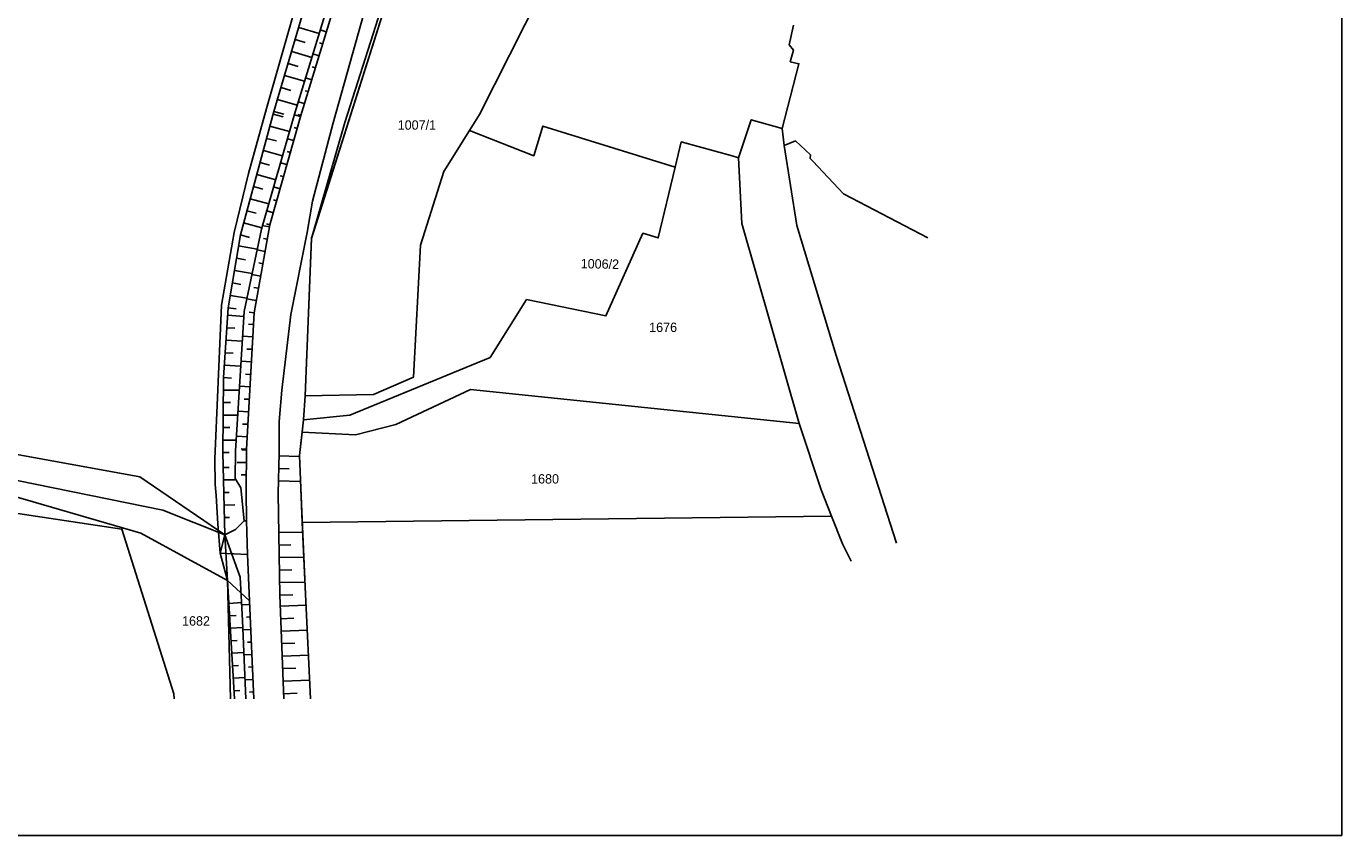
# Model space of a CAD drawing. Extents: x -583470 to -583050, y -1165714 to -1165417.
# Drawn here: x -583260.4 to -583050.1, y -1165714.3 to -1165584.9 of the extents above; entities that cross this region are included whole.
import ezdxf

# ---------------------------------------------------------------- set-up
doc = ezdxf.new("R2010")
doc.units = 0
for name, color, linetype in [('21', 7, 'Continuous'), ('37', 7, 'Continuous'), ('38', 7, 'Continuous'), ('42', 7, 'Continuous'), ('60', 7, 'Continuous'), ('62', 7, 'Continuous'), ('Kabel_soucasny', 7, 'Continuous'), ('Rám', 7, 'Continuous'), ('Šrafy', 7, 'Continuous')]:
    doc.layers.add(name, color=color, linetype=linetype)

msp = doc.modelspace()

# ---------------------------------------------------------------- linework, layer by layer
msp.add_lwpolyline([(-583050.1, -1165714.31), (-583470.1, -1165714.31), (-583470.1, -1165417.31), (-583050.1, -1165417.31)], close=True)
at = {"layer": '21'}
for points in [[(-583228.99, -1165653.07), (-583228.87, -1165641.09), (-583228.11, -1165629.9), (-583226.18, -1165618.27), (-583220.81, -1165598.53), (-583210.74, -1165564.34), (-583206.27, -1165549.49), (-583193.05, -1165509.63), (-583187.62, -1165491.96), (-583180.14, -1165470.95), (-583173.68, -1165449.56)], [(-583197.17, -1165563.17), (-583214.79, -1165618.82), (-583215.85, -1165644.01)], [(-583215.85, -1165644.01), (-583216.1, -1165647.85)], [(-583216.74, -1165653.51), (-583216.1, -1165647.85)], [(-583228.99, -1165653.07), (-583228.69, -1165666.2)], [(-583216.43, -1165661.3), (-583216.74, -1165653.51)], [(-583214.97, -1165692.44), (-583215.79, -1165675.68), (-583216.43, -1165661.3)], [(-583228.25, -1165673.5), (-583228.69, -1165666.2)], [(-583227.11, -1165692.44), (-583228.25, -1165673.5)]]:
    msp.add_lwpolyline(points, dxfattribs=at)
at = {"layer": '37'}
msp.add_lwpolyline([(-583225.23, -1165664), (-583225.6, -1165663.97)], dxfattribs=at)
at = {"layer": '38'}
for points in [[(-583175.32, -1165449.44), (-583181.94, -1165470.41), (-583188.9, -1165491.39), (-583194.56, -1165508.91), (-583207.56, -1165548.63), (-583212.15, -1165563.51), (-583221.98, -1165598.06), (-583224.87, -1165608.46), (-583227.16, -1165617.88), (-583229.21, -1165629.48), (-583230.26, -1165654.06)], [(-583230.26, -1165654.06), (-583230.19, -1165658.17), (-583230.05, -1165659.91), (-583229.77, -1165664.47), (-583229.4, -1165669.14), (-583228.25, -1165673.5)], [(-583228.69, -1165666.2), (-583226.94, -1165665.36), (-583225.6, -1165663.97)], [(-583229.4, -1165669.14), (-583228.69, -1165666.2)], [(-583229.4, -1165669.14), (-583225.03, -1165669.36)], [(-583227.77, -1165692.44), (-583228.25, -1165673.5)]]:
    msp.add_lwpolyline(points, dxfattribs=at)
at = {"layer": '42'}
for points in [[(-583171.13, -1165449.75), (-583178.31, -1165472.16), (-583184.97, -1165493.01), (-583190.34, -1165511.2), (-583202.91, -1165551.09), (-583207.05, -1165564.64), (-583217.53, -1165598.97), (-583222.81, -1165617.33), (-583225.6, -1165630.49), (-583226.96, -1165652.83), (-583227.01, -1165657.21), (-583226.1, -1165658.69), (-583225.6, -1165663.97)], [(-583209.49, -1165600.28), (-583201.68, -1165575.91), (-583199.68, -1165567.9)], [(-583214.79, -1165618.82), (-583209.49, -1165600.28)], [(-583225.84, -1165679.92), (-583225.33, -1165692.44)]]:
    msp.add_lwpolyline(points, dxfattribs=at)
at = {"layer": '60'}
for points in [[(-583216.85, -1165585.1), (-583213.59, -1165586.06)], [(-583212.44, -1165585.8), (-583213.42, -1165585.5)], [(-583217.42, -1165587.02), (-583215.8, -1165587.5)], [(-583213.02, -1165587.71), (-583213.51, -1165587.56)], [(-583217.98, -1165588.94), (-583214.76, -1165589.89)], [(-583213.6, -1165589.62), (-583214.59, -1165589.33)], [(-583218.55, -1165590.86), (-583216.95, -1165591.33)], [(-583214.19, -1165591.54), (-583214.68, -1165591.39)], [(-583219.11, -1165592.77), (-583215.93, -1165593.71)], [(-583214.77, -1165593.45), (-583215.75, -1165593.15)], [(-583219.68, -1165594.69), (-583218.09, -1165595.16)], [(-583215.35, -1165595.36), (-583215.85, -1165595.21)], [(-583220.24, -1165596.61), (-583217.09, -1165597.54)], [(-583215.94, -1165597.28), (-583216.92, -1165596.98)], [(-583220.93, -1165598.97), (-583219.35, -1165599.4)], [(-583220.81, -1165598.53), (-583219.24, -1165598.99)], [(-583216.56, -1165599.33), (-583217.55, -1165599.05)], [(-583216.52, -1165599.19), (-583217.01, -1165599.04)], [(-583221.46, -1165600.9), (-583218.33, -1165601.75)], [(-583217.1, -1165601.25), (-583217.6, -1165601.11)], [(-583221.98, -1165602.83), (-583220.43, -1165603.25)], [(-583217.65, -1165603.18), (-583218.66, -1165602.89)], [(-583223.03, -1165606.69), (-583221.51, -1165607.1)], [(-583222.51, -1165604.76), (-583219.44, -1165605.6)], [(-583218.19, -1165605.1), (-583218.7, -1165604.96)], [(-583223.56, -1165608.62), (-583220.54, -1165609.44)], [(-583218.73, -1165607.03), (-583219.76, -1165606.74)], [(-583224.08, -1165610.55), (-583222.59, -1165610.96)], [(-583219.82, -1165610.88), (-583220.87, -1165610.58)], [(-583219.28, -1165608.95), (-583219.8, -1165608.8)], [(-583224.61, -1165612.48), (-583221.65, -1165613.29)], [(-583220.36, -1165612.8), (-583220.89, -1165612.65)], [(-583225.13, -1165614.41), (-583223.66, -1165614.81)], [(-583220.91, -1165614.73), (-583221.97, -1165614.42)], [(-583225.66, -1165616.34), (-583222.75, -1165617.13)], [(-583221.51, -1165616.96), (-583222.69, -1165616.75)], [(-583221.45, -1165616.65), (-583221.99, -1165616.5)], [(-583226.18, -1165618.27), (-583224.74, -1165618.66)], [(-583221.86, -1165618.93), (-583222.48, -1165618.82)], [(-583226.47, -1165620.03), (-583223.49, -1165620.53)], [(-583222.22, -1165620.9), (-583223.52, -1165620.66)], [(-583226.8, -1165622.01), (-583225.35, -1165622.25)], [(-583222.57, -1165622.87), (-583223.25, -1165622.74)], [(-583227.13, -1165623.98), (-583224.32, -1165624.45)], [(-583222.93, -1165624.84), (-583224.35, -1165624.58)], [(-583227.46, -1165625.95), (-583226.09, -1165626.18)], [(-583223.28, -1165626.8), (-583224.02, -1165626.67)], [(-583227.78, -1165627.93), (-583225.15, -1165628.36)], [(-583223.64, -1165628.77), (-583225.18, -1165628.49)], [(-583228.19, -1165631.11), (-583225.65, -1165631.29)], [(-583228.11, -1165629.9), (-583226.84, -1165630.11)], [(-583223.99, -1165630.74), (-583224.79, -1165630.6)], [(-583228.33, -1165633.11), (-583227.05, -1165633.19)], [(-583224.09, -1165632.57), (-583224.91, -1165632.53)], [(-583228.46, -1165635.1), (-583225.91, -1165635.28)], [(-583224.2, -1165634.57), (-583225.84, -1165634.48)], [(-583228.6, -1165637.1), (-583227.32, -1165637.19)], [(-583224.31, -1165636.56), (-583225.14, -1165636.52)], [(-583228.73, -1165639.09), (-583226.16, -1165639.27)], [(-583224.42, -1165638.56), (-583226.09, -1165638.47)], [(-583228.87, -1165641.09), (-583227.58, -1165641.18)], [(-583224.53, -1165640.56), (-583225.37, -1165640.51)], [(-583228.89, -1165643.07), (-583226.46, -1165643.09)], [(-583224.63, -1165642.55), (-583226.33, -1165642.46)], [(-583224.74, -1165644.55), (-583225.6, -1165644.51)], [(-583228.91, -1165645.07), (-583227.74, -1165645.08)], [(-583224.85, -1165646.55), (-583226.57, -1165646.46)], [(-583228.93, -1165647.07), (-583226.67, -1165647.09)], [(-583224.96, -1165648.55), (-583225.83, -1165648.5)], [(-583228.95, -1165649.07), (-583227.86, -1165649.08)], [(-583225.07, -1165650.54), (-583226.81, -1165650.45)], [(-583228.97, -1165651.07), (-583226.87, -1165651.09)], [(-583225.18, -1165652.54), (-583226.06, -1165652.49)], [(-583225.25, -1165652.65), (-583225.94, -1165652.65)], [(-583228.99, -1165653.07), (-583227.98, -1165653.08)], [(-583225.25, -1165654.65), (-583226.72, -1165654.65)], [(-583219.97, -1165653.61), (-583216.84, -1165653.7)], [(-583228.93, -1165655.45), (-583228, -1165655.43)], [(-583225.25, -1165656.65), (-583226.04, -1165656.65)], [(-583220.03, -1165655.61), (-583218.38, -1165655.66)], [(-583228.87, -1165657.45), (-583227.07, -1165657.41)], [(-583220.09, -1165657.61), (-583216.61, -1165657.71)], [(-583228.82, -1165659.45), (-583227.95, -1165659.43)], [(-583228.77, -1165661.45), (-583227.07, -1165661.41)], [(-583228.72, -1165663.45), (-583227.9, -1165663.43)], [(-583220.09, -1165665.86), (-583216.32, -1165665.78)], [(-583220.04, -1165667.86), (-583218.13, -1165667.82)], [(-583220, -1165669.86), (-583216.11, -1165669.77)], [(-583219.95, -1165671.86), (-583217.97, -1165671.82)], [(-583219.91, -1165673.86), (-583215.89, -1165673.77)], [(-583219.86, -1165675.86), (-583217.82, -1165675.81)], [(-583228.01, -1165677.17), (-583225.96, -1165677.04)], [(-583224.69, -1165677.35), (-583225.94, -1165677.41)], [(-583219.8, -1165677.62), (-583215.59, -1165677.46)], [(-583227.89, -1165679.16), (-583226.88, -1165679.1)], [(-583224.61, -1165679.35), (-583225.23, -1165679.38)], [(-583219.72, -1165679.62), (-583217.61, -1165679.54)], [(-583227.77, -1165681.16), (-583225.79, -1165681.04)], [(-583224.52, -1165681.35), (-583225.78, -1165681.41)], [(-583219.65, -1165681.61), (-583215.42, -1165681.46)], [(-583227.66, -1165683.16), (-583226.68, -1165683.1)], [(-583224.44, -1165683.35), (-583225.07, -1165683.38)], [(-583219.57, -1165683.61), (-583217.45, -1165683.54)], [(-583227.54, -1165685.15), (-583225.63, -1165685.04)], [(-583224.35, -1165685.35), (-583225.62, -1165685.4)], [(-583219.5, -1165685.61), (-583215.24, -1165685.46)], [(-583227.42, -1165687.15), (-583226.48, -1165687.09)], [(-583224.26, -1165687.34), (-583224.9, -1165687.37)], [(-583219.43, -1165687.61), (-583217.29, -1165687.53)], [(-583227.3, -1165689.14), (-583225.47, -1165689.04)], [(-583224.18, -1165689.34), (-583225.46, -1165689.4)], [(-583219.35, -1165689.61), (-583215.06, -1165689.45)], [(-583227.18, -1165691.14), (-583226.29, -1165691.09)], [(-583224.09, -1165691.34), (-583224.73, -1165691.37)], [(-583219.28, -1165691.61), (-583217.12, -1165691.53)]]:
    msp.add_lwpolyline(points, dxfattribs=at)
at = {"layer": '62'}
for points in [[(-583371.79, -1165638.08), (-583361.74, -1165641.15), (-583346.91, -1165644.58), (-583323.24, -1165647.92), (-583297.05, -1165651.52), (-583281.69, -1165654.07), (-583264.82, -1165656.96), (-583238.56, -1165662.27)], [(-583372.12, -1165641.43), (-583362.92, -1165643.19), (-583347.12, -1165647.36), (-583324.02, -1165650.58), (-583297.11, -1165654.42), (-583282.31, -1165656.2), (-583265.24, -1165659.25), (-583242.08, -1165665.94)], [(-583228.69, -1165666.2), (-583238.56, -1165662.27)], [(-583242.08, -1165665.94), (-583228.25, -1165673.5)], [(-583228.25, -1165673.5), (-583224.72, -1165676.77)]]:
    msp.add_lwpolyline(points, dxfattribs=at)
at = {"layer": 'Rám'}
for p, q in [((-583139.23, -1165603.98), (-583139.56, -1165601.27)), ((-583216.1, -1165647.85), (-583215.85, -1165644.01)), ((-583216.32, -1165649.81), (-583216.1, -1165647.85)), ((-583216.29, -1165664.24), (-583131.67, -1165663.22))]:
    msp.add_line(p, q, dxfattribs=at)
for points in [[(-583202.69, -1165538.68), (-583205.32, -1165546.6), (-583206.27, -1165549.49), (-583206.64, -1165550.7), (-583210.74, -1165564.34), (-583220.81, -1165598.53), (-583226.18, -1165618.27), (-583228.11, -1165629.9), (-583228.87, -1165641.09), (-583228.99, -1165653.07), (-583228.69, -1165666.2)], [(-583197.17, -1165563.17), (-583214.81, -1165618.81), (-583215.85, -1165644.01)], [(-583189.56, -1165601.59), (-583187.95, -1165599), (-583178.29, -1165579.88), (-583175.8, -1165571.71), (-583174.14, -1165566.51)], [(-583137.75, -1165584.74), (-583138.42, -1165587.89), (-583137.75, -1165588.71), (-583138.26, -1165590.59), (-583136.89, -1165590.9), (-583139.56, -1165601.27)], [(-583139.56, -1165601.27), (-583144.49, -1165599.85), (-583146.52, -1165605.94)], [(-583215.85, -1165644.01), (-583204.91, -1165643.79), (-583198.49, -1165641), (-583197.36, -1165619.92), (-583193.63, -1165608.15), (-583189.56, -1165601.59)], [(-583189.56, -1165601.59), (-583179.27, -1165605.61), (-583177.81, -1165600.88), (-583156.66, -1165607.42)], [(-583146.52, -1165605.94), (-583147.56, -1165605.65), (-583155.7, -1165603.4), (-583156.66, -1165607.42)], [(-583116.25, -1165618.75), (-583129.73, -1165611.71), (-583134.65, -1165606.49), (-583135.09, -1165606.03), (-583135.03, -1165605.47), (-583137.42, -1165603.24), (-583139.23, -1165603.98)], [(-583121.26, -1165667.54), (-583130.91, -1165637.56), (-583137.23, -1165616.79), (-583139.23, -1165603.98)], [(-583136.85, -1165648.41), (-583146.03, -1165616.46), (-583146.52, -1165605.94)], [(-583156.66, -1165607.42), (-583159.38, -1165618.75), (-583161.81, -1165618), (-583167.75, -1165631.23), (-583180.41, -1165628.61), (-583186.27, -1165637.89), (-583208.68, -1165647.1), (-583216.1, -1165647.85)], [(-583352.56, -1165623.43), (-583338.23, -1165642.98), (-583317.68, -1165646.22), (-583282.91, -1165650.36), (-583267.19, -1165652.43), (-583242.28, -1165656.94), (-583228.69, -1165666.2)], [(-583216.32, -1165649.81), (-583207.78, -1165650.22), (-583201.32, -1165648.6), (-583189.4, -1165642.98), (-583136.85, -1165648.41)], [(-583136.85, -1165648.41), (-583133.34, -1165659.02), (-583131.67, -1165663.22)], [(-583216.29, -1165664.24), (-583216.58, -1165657.4), (-583216.74, -1165653.51), (-583216.32, -1165649.81)], [(-583374.25, -1165656.58), (-583351.23, -1165657.59), (-583331.17, -1165652.35), (-583245.16, -1165665.31), (-583236.84, -1165691.62), (-583236.79, -1165692.44)], [(-583131.67, -1165663.22), (-583129.91, -1165667.64), (-583128.54, -1165670.45)], [(-583214.99, -1165692.44), (-583215.79, -1165675.68), (-583216.29, -1165664.24)], [(-583228.69, -1165666.2), (-583226.21, -1165672.99), (-583225.84, -1165679.92), (-583225.32, -1165692.44)]]:
    msp.add_lwpolyline(points, dxfattribs=at)
at = {"layer": 'Šrafy'}
for points in [[(-583170.1, -1165449.82), (-583177.59, -1165472.81), (-583183.72, -1165493.32), (-583189.54, -1165511.52), (-583201.76, -1165551.48), (-583206.07, -1165564.92), (-583216.52, -1165599.19), (-583221.45, -1165616.65), (-583223.99, -1165630.74), (-583225.18, -1165652.54), (-583225.28, -1165659.24), (-583225.23, -1165664)], [(-583220.15, -1165659.61), (-583219.96, -1165653.11), (-583219.97, -1165648.1), (-583219.57, -1165643.1), (-583218.09, -1165630.97), (-583215.53, -1165617.89), (-583214.66, -1165612.9), (-583211.33, -1165600.33), (-583206.01, -1165581.38), (-583200.39, -1165564.2), (-583196.56, -1165552.55), (-583195.08, -1165547.77), (-583192.01, -1165536.91), (-583188.64, -1165525.84), (-583184.8, -1165513.4), (-583179.16, -1165495.16), (-583172.78, -1165474.89), (-583165.04, -1165450.2)], [(-583219.25, -1165692.44), (-583219.86, -1165675.86), (-583220.15, -1165659.61)], [(-583225.03, -1165669.36), (-583225.23, -1165664)], [(-583225.03, -1165669.36), (-583224.72, -1165676.77), (-583224.04, -1165692.44)]]:
    msp.add_lwpolyline(points, dxfattribs=at)

# ---------------------------------------------------------------- texts
at = {"layer": 'Kabel_soucasny'}
for s, p in [('1007/1', (-583201.03, -1165601.45)), ('1676', (-583160.82, -1165633.79)), ('1680', (-583179.7, -1165658.02)), ('1682', (-583235.51, -1165680.73))]:
    msp.add_text(s, height=1.5, dxfattribs=at).set_placement(p)
msp.add_text('1006/2', height=1.5, rotation=359, dxfattribs=at).set_placement((-583171.78, -1165623.6))

doc.saveas('drawing.dxf')
